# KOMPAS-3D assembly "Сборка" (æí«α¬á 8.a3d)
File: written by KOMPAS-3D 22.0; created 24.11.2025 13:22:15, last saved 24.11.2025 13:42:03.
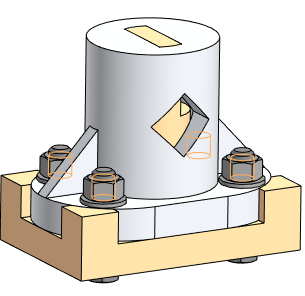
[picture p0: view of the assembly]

Document properties: Автор: alymovy@yandex.ru; Организация: HP; Полное имя файла: C:\Для ноута\Инженерная графика\ППЭ 2025-2026\Варианты 1-38\Вариант 8 СБ\Вар 8 СБ\Сборка 8.a3d

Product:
- Component [detail]: Основание  | designation Вариант 8  | qty 1  | Масса: 3.587615; source file: Основание вар 8.m3d
- Component [detail]: Корпус вар 8  | qty 1  | Масса: 3.880901; source file: Корпус вар 8.m3d
- Component [detail]: Болт М14x60 ГОСТ 15591-70  | qty 4  | Масса: 0.091885; source file: Болт М14x60 ГОСТ 15591-70.m3d
- Component [detail]: Сборка  | qty 4  | Масса: 0.008612; source file: Шайба 14.m3d
- Component [detail]: Сборка  | qty 4  | Масса: 0.02533; source file: Гайка М14.m3d
- Part/product: Сборка
    Масса: 7.971823

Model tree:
1. Массив по сетке:1  (with: Элемент выдавливания:2, Элемент выдавливания:1, Операция без истории:1, Элемент выдавливания:6, Элемент выдавливания:3)  (labels: Фаска:3)  (4 pattern instances)
     Шаг 1 = 95; Угол раствора = 90; Шаг 2 = 53.62

Referenced files in C:\Для ноута\Инженерная графика\ППЭ 2025-2026\Варианты 1-38\Вариант 8 СБ\Вар 8 СБ\: Основание вар 8.m3d, Корпус вар 8.m3d, Болт М14x60 ГОСТ 15591-70.m3d, Шайба 14.m3d, Гайка М14.m3d
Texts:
  Вариант 8 Основание
  Корпус вар 8 Корпус вар 8
  Болт М14x60 ГОСТ 15591-70 (1)
  Сборка (1)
